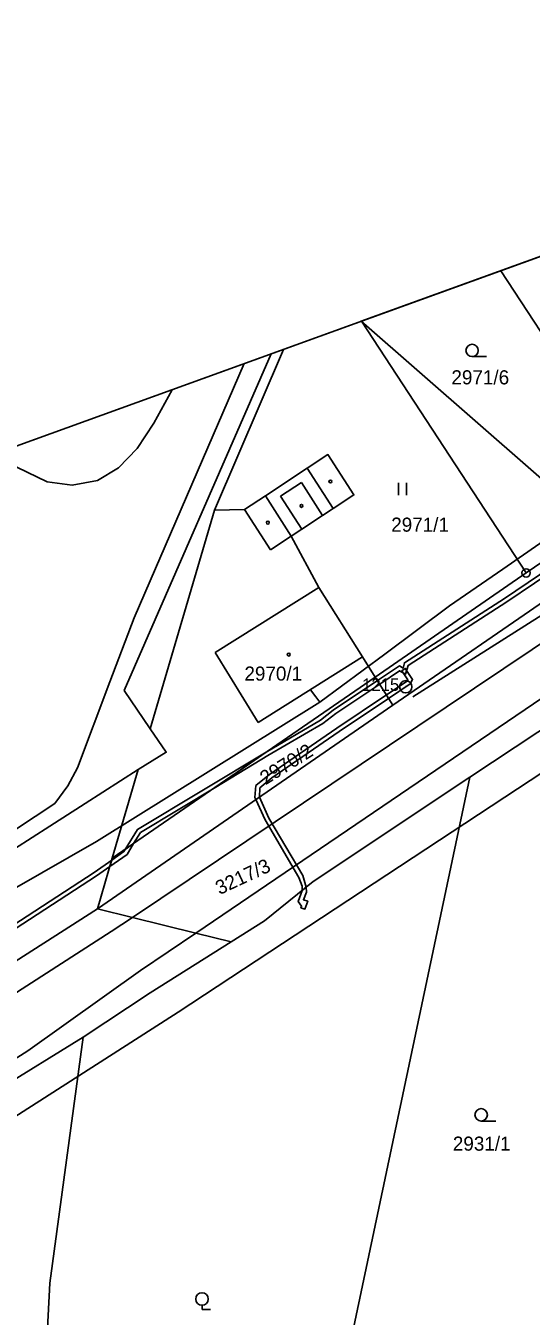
# Model space of a CAD drawing. Extents: x -620552 to -620056, y -1123312 to -1122890.
# Drawn here: x -620295.9 to -620235.1, y -1123045.1 to -1122889.6 of the extents above; entities that cross this region are included whole.
import ezdxf

# ---------------------------------------------------------------- set-up
doc = ezdxf.new("R2010")
doc.units = 0
for name, color, linetype in [('CETIN', 7, 'Continuous'), ('Hranice parcel', 7, 'Continuous'), ('Parcelní čísla', 7, 'Continuous'), ('Rámečky', 7, 'Continuous'), ('Rámečky-tisk', 7, 'Continuous'), ('VAS vodovod', 7, 'Continuous'), ('Vnitřní kresba', 7, 'Continuous'), ('Věcná břemena k části', 7, 'Continuous'), ('Značky bodu BP', 7, 'Continuous'), ('Značky budov', 7, 'Continuous'), ('Značky kultur', 7, 'Continuous')]:
    doc.layers.add(name, color=color, linetype=linetype)

msp = doc.modelspace()

# ---------------------------------------------------------------- linework, layer by layer
at = {"layer": 'CETIN'}
for points in [[(-620249.32, -1122970.47), (-620218.63, -1122950.99), (-620187.55, -1122931.18), (-620162.84, -1122907.83)], [(-620523.51, -1123111.55), (-620453.59, -1123102.46), (-620423.24, -1123094.92), (-620404.67, -1123086.51), (-620368.95, -1123067.06), (-620277.61, -1123008.49), (-620145.62, -1122921.55)]]:
    msp.add_lwpolyline(points, dxfattribs=at)
at = {"layer": 'Hranice parcel'}
for p, q in [((-620235.69, -1122955.55), (-620255.53, -1122925.21)), ((-620273.22, -1122947.97), (-620264.92, -1122928.61)), ((-620251.74, -1122971.48), (-620208, -1122941.31)), ((-620221.39, -1122945.68), (-620235.69, -1122955.55)), ((-620253.87, -1122968.1), (-620235.69, -1122955.55)), ((-620218.17, -1122964.05), (-620242.46, -1122980.18)), ((-620285.54, -1122989.95), (-620253.87, -1122968.1)), ((-620251.74, -1122971.48), (-620253.87, -1122968.1)), ((-620287.33, -1122996.04), (-620251.74, -1122971.48)), ((-620369, -1123034.76), (-620282.4, -1122979.23)), ((-620282.4, -1122979.23), (-620285.54, -1122989.95)), ((-620263.28, -1123078.74), (-620242.46, -1122980.18)), ((-620285.54, -1122989.95), (-620287.33, -1122996.04)), ((-620280.96, -1123006.18), (-620289.02, -1123011.5)), ((-620289.02, -1123011.5), (-620330.98, -1123037.45))]:
    msp.add_line(p, q, dxfattribs=at)
for points in [[(-620238.74, -1122919.13), (-620229.95, -1122932.57), (-620221.39, -1122945.68)], [(-620253.87, -1122968.1), (-620255.41, -1122965.65), (-620260.66, -1122957.29), (-620263.97, -1122951.11), (-620262.72, -1122950.29), (-620260.22, -1122948.64), (-620258.93, -1122947.79), (-620256.43, -1122946.15), (-620259.56, -1122941.28), (-620262.06, -1122942.93), (-620267.1, -1122946.24), (-620269.6, -1122947.89), (-620273.22, -1122947.97)], [(-620282.4, -1122979.23), (-620279.03, -1122977.17), (-620280.97, -1122974.36), (-620273.22, -1122947.97)], [(-620242.46, -1122980.18), (-620261.36, -1122992.76), (-620267.21, -1122997.48)], [(-620365.22, -1123044.99), (-620354.45, -1123039), (-620287.33, -1122996.04)], [(-620267.21, -1122997.48), (-620271.2, -1123000), (-620280.96, -1123006.18)], [(-620289.02, -1123011.5), (-620293.05, -1123041.17), (-620295.61, -1123091.1), (-620294.3, -1123096.22)]]:
    msp.add_lwpolyline(points, dxfattribs=at)
at = {"layer": 'Rámečky'}
msp.add_line((-620157.19, -1122889.6), (-620552.1, -1123032.6), dxfattribs=at)
for points in [[(-620126.7, -1122973.8), (-620157.19, -1122889.6), (-620255.57, -1122925.22)], [(-620255.57, -1122925.22), (-620158.49, -1123010.14), (-620126.7, -1122973.8)]]:
    msp.add_lwpolyline(points, dxfattribs=at)
at = {"layer": 'Rámečky-tisk'}
for points in [[(-620450.98, -1123311.85), (-620056.07, -1123168.86), (-620157.19, -1122889.6), (-620552.1, -1123032.6)], [(-620126.7, -1122973.8), (-620157.19, -1122889.6), (-620255.57, -1122925.22)], [(-620255.57, -1122925.22), (-620158.49, -1123010.14), (-620126.7, -1122973.8)]]:
    msp.add_lwpolyline(points, dxfattribs=at)
at = {"layer": 'VAS vodovod'}
for points in [[(-620232.06, -1122950.65), (-620238.49, -1122955.08), (-620244.93, -1122959.52), (-620252.72, -1122965.33), (-620260.52, -1122971.14)], [(-620260.52, -1122971.14), (-620273.97, -1122979.53), (-620287.42, -1122987.93), (-620297.29, -1122993.57), (-620307.15, -1122999.21), (-620314.18, -1123003.29), (-620314.33, -1123003.39), (-620314.47, -1123003.48), (-620314.66, -1123003.17), (-620315.7, -1123001.56), (-620316.76, -1122999.96), (-620318.4, -1122997.49), (-620320.04, -1122995.03), (-620321.07, -1122993.52), (-620323.65, -1122991.1), (-620326.23, -1122988.68), (-620330.65, -1122984.59), (-620335.07, -1122980.5), (-620339.44, -1122976.42), (-620343.82, -1122972.33), (-620352.52, -1122964.33), (-620355.63, -1122961.46)], [(-620260.52, -1122971.14), (-620260.54, -1122971.11), (-620261.02, -1122970.49), (-620261.67, -1122969.65)]]:
    msp.add_lwpolyline(points, dxfattribs=at)
at = {"layer": 'Vnitřní kresba'}
for p, q in [((-620266.41, -1122929.15), (-620284.09, -1122969.72)), ((-620282.88, -1122960.95), (-620269.65, -1122930.32)), ((-620280.53, -1122937.51), (-620278.32, -1122933.46)), ((-620282.53, -1122940.57), (-620280.53, -1122937.51)), ((-620300.01, -1122941.39), (-620293.37, -1122944.55)), ((-620284.77, -1122942.9), (-620282.53, -1122940.57)), ((-620287.32, -1122944.4), (-620284.77, -1122942.9)), ((-620262.06, -1122942.93), (-620258.93, -1122947.79)), ((-620290.35, -1122944.97), (-620287.32, -1122944.4)), ((-620293.37, -1122944.55), (-620290.35, -1122944.97)), ((-620265.27, -1122946.29), (-620262.76, -1122944.66)), ((-620262.76, -1122944.66), (-620260.22, -1122948.64)), ((-620267.1, -1122946.24), (-620263.97, -1122951.11)), ((-620262.72, -1122950.29), (-620265.27, -1122946.29)), ((-620269.6, -1122947.89), (-620266.47, -1122952.75)), ((-620266.47, -1122952.75), (-620263.97, -1122951.11)), ((-620224.19, -1122957.54), (-620283.1, -1122997.08)), ((-620273.13, -1122965.13), (-620260.66, -1122957.29)), ((-620285.84, -1122968.66), (-620282.88, -1122960.95)), ((-620220.18, -1122961.38), (-620275.49, -1122998.97)), ((-620267.97, -1122973.56), (-620273.13, -1122965.13)), ((-620255.41, -1122965.65), (-620267.97, -1122973.56)), ((-620289.73, -1122979.06), (-620285.84, -1122968.66)), ((-620284.09, -1122969.72), (-620280.97, -1122974.36)), ((-620290.87, -1122981.21), (-620289.73, -1122979.06)), ((-620292.44, -1122983.33), (-620290.87, -1122981.21)), ((-620307.51, -1122993.27), (-620292.44, -1122983.33)), ((-620287.33, -1122996.04), (-620283.1, -1122997.08)), ((-620283.1, -1122997.08), (-620285.65, -1122998.79)), ((-620283.1, -1122997.08), (-620275.49, -1122998.97)), ((-620336.04, -1123031.13), (-620285.65, -1122998.79)), ((-620282.13, -1123003.48), (-620275.49, -1122998.97)), ((-620275.49, -1122998.97), (-620271.2, -1123000)), ((-620295.72, -1123013.16), (-620282.13, -1123003.48)), ((-620339.98, -1123041.29), (-620295.72, -1123013.16))]:
    msp.add_line(p, q, dxfattribs=at)
at = {"layer": 'Věcná břemena k části'}
msp.add_lwpolyline([(-620221.44, -1122947.23), (-620238.3, -1122958.63), (-620250.35, -1122966.38), (-620250.52, -1122967.01), (-620250.96, -1122966.76), (-620253.6, -1122968.53), (-620258.92, -1122972.11), (-620260.46, -1122973.29), (-620267, -1122977.16), (-620273.08, -1122981.36), (-620266.78, -1122977.55), (-620260.18, -1122973.71), (-620258.62, -1122972.51), (-620253.33, -1122968.95), (-620250.94, -1122967.34), (-620250.2, -1122967.75), (-620249.91, -1122966.7), (-620238.02, -1122959.05), (-620221.34, -1122947.77)], dxfattribs=at)
for points in [[(-620267.76, -1122981.44), (-620266.3, -1122980.23), (-620258.21, -1122974.67), (-620252.25, -1122970.68), (-620249.64, -1122968.93), (-620249.36, -1122968.41), (-620250.25, -1122967.05), (-620250.66, -1122967.34), (-620249.94, -1122968.43), (-620250.02, -1122968.59), (-620252.51, -1122970.26), (-620258.49, -1122974.25), (-620266.6, -1122979.83), (-620268.24, -1122981.19), (-620268.35, -1122982.6), (-620268.23, -1122982.86), (-620267.82, -1122982.58)], [(-620282.15, -1122986.83), (-620273.08, -1122981.36), (-620267, -1122977.16), (-620282.51, -1122986.47), (-620283.97, -1122988.87), (-620282.96, -1122988.17)], [(-620262.66, -1122993.81), (-620262.17, -1122993.41), (-620262.59, -1122992.04), (-620266.69, -1122985.11), (-620267.82, -1122982.58), (-620268.23, -1122982.86), (-620267.13, -1122985.33), (-620263.05, -1122992.26), (-620262.67, -1122993.31)], [(-620283.75, -1122989.47), (-620282.96, -1122988.17), (-620283.97, -1122988.87), (-620284.13, -1122989.13), (-620285.6, -1122990.17), (-620285.83, -1122990.94)], [(-620359.12, -1123037.46), (-620340.69, -1123026.08), (-620322.75, -1123014.93), (-620304.43, -1123003.11), (-620287.42, -1122992.06), (-620285.83, -1122990.94), (-620285.6, -1122990.17), (-620287.7, -1122991.64), (-620304.71, -1123002.69), (-620323.01, -1123014.51), (-620340.95, -1123025.66), (-620359.38, -1123037.04), (-620368.18, -1123042.28), (-620367.79, -1123042.63)], [(-620262.66, -1122993.81), (-620263.14, -1122995.17), (-620262.74, -1122995.71), (-620262.81, -1122995.9), (-620262.34, -1122996.07), (-620262, -1122995.13), (-620262.52, -1122994.94), (-620262.16, -1122994.01), (-620262.17, -1122993.41)]]:
    msp.add_lwpolyline(points, close=True, dxfattribs=at)
at = {"layer": 'Značky bodu BP'}
for centre, radius in [((-620235.69, -1122955.55), 0.5), ((-620235.69, -1122955.55), 0.0303), ((-620250.19, -1122969.27), 0.75), ((-620250.19, -1122969.27), 0.03)]:
    msp.add_circle(centre, radius, dxfattribs=at)
at = {"layer": 'Značky budov'}
for centre in [(-620259.26, -1122944.53), (-620262.75, -1122947.47), (-620266.8, -1122949.49), (-620264.28, -1122965.39)]:
    msp.add_circle(centre, 0.175, dxfattribs=at)
at = {"layer": 'Značky kultur'}
for p, q in [((-620242.2, -1122929.48), (-620240.45, -1122929.48)), ((-620251.08, -1122946.18), (-620251.08, -1122944.68)), ((-620250.08, -1122946.18), (-620250.08, -1122944.68)), ((-620241.1, -1123021.62), (-620239.35, -1123021.62)), ((-620274.72, -1123043.82), (-620274.72, -1123044.32)), ((-620274.72, -1123044.32), (-620273.72, -1123044.32))]:
    msp.add_line(p, q, dxfattribs=at)
for centre in [(-620242.2, -1122928.73), (-620241.1, -1123020.87), (-620274.72, -1123043.07)]:
    msp.add_circle(centre, 0.75, dxfattribs=at)

# ---------------------------------------------------------------- texts
at = {"layer": 'Parcelní čísla'}
for s, p in [('2971/6', (-620244.69, -1122932.82)), ('2971/1', (-620251.94, -1122950.58)), ('2970/1', (-620269.62, -1122968.53)), ('2931/1', (-620244.52, -1123025.19))]:
    msp.add_text(s, height=1.7, dxfattribs=at).set_placement(p)
for s, rotation, p in [('2970/2', 32, (-620267.08, -1122981.16)), ('3217/3', 25, (-620272.61, -1122994.39))]:
    msp.add_text(s, height=1.7, rotation=rotation, dxfattribs=at).set_placement(p)
at = {"layer": 'Značky bodu BP'}
msp.add_text('1215', height=1.5, dxfattribs=at).set_placement((-620255.44, -1122969.77))

doc.saveas('drawing.dxf')
